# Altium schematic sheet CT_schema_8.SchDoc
size 252 x 159 mm
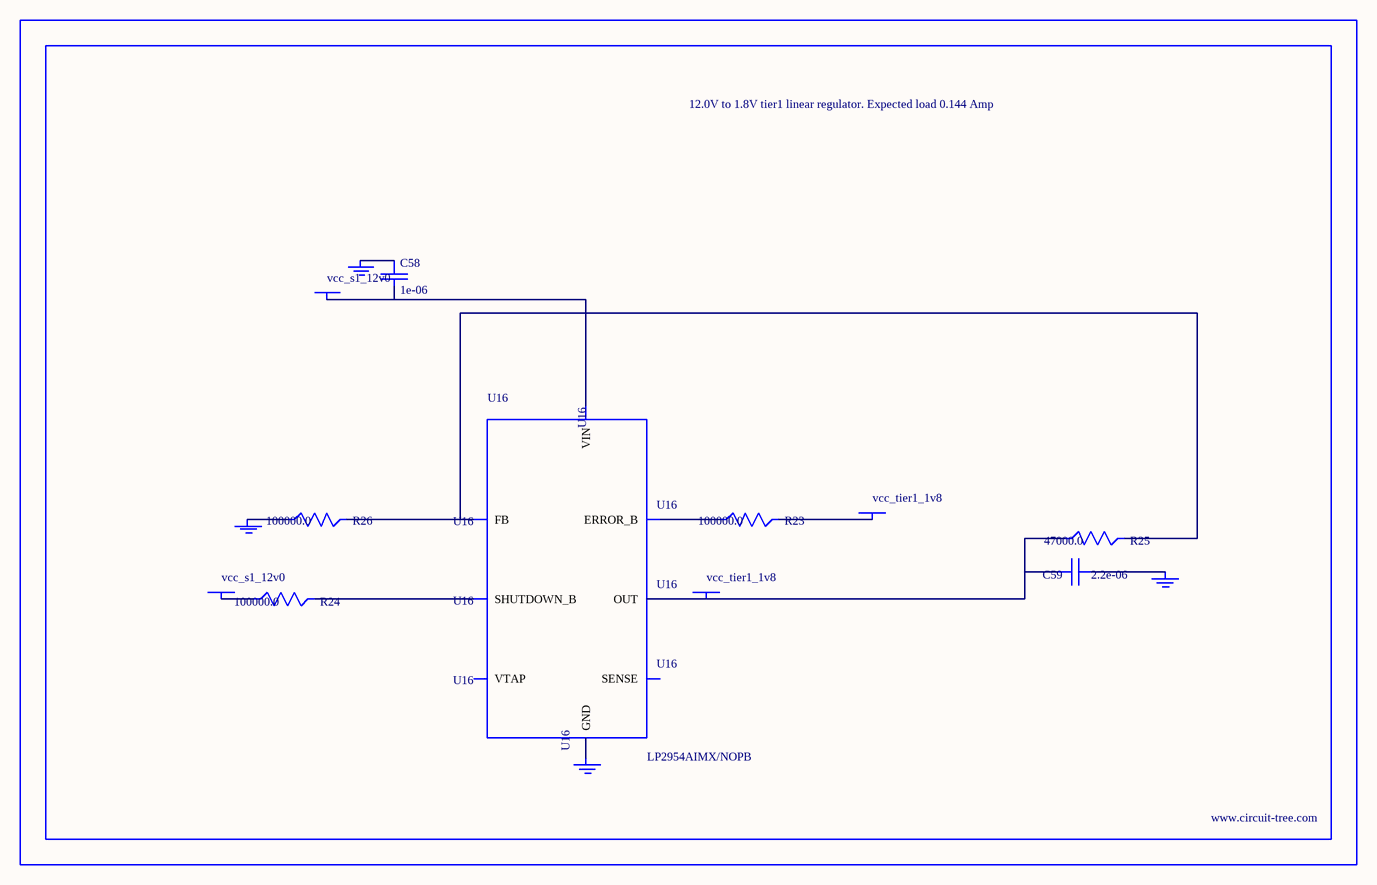
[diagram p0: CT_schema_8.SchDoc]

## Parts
BORDER7  (no value)
C58  1e-06  [EXV-9B]
C59  2.2e-06  [EXV-9B]
GND_INSTANCE_7_0  (no value)
GND_INSTANCE_7_1  (no value)
GND_INSTANCE_7_2  (no value)
GND_INSTANCE_7_3  (no value)
POWER_INSTANCE_7_0  vcc_s1_12v0
POWER_INSTANCE_7_1  vcc_tier1_1v8
POWER_INSTANCE_7_2  vcc_s1_12v0
POWER_INSTANCE_7_3  vcc_tier1_1v8
R23  100000.0  [R0603]
R24  100000.0  [R0603]
R25  47000.0  [R0603]
R26  100000.0  [R0603]
U16  LP2954AIMX/NOPB  [LP2954]

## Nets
NetC58_1: C58.1 GND_INSTANCE_7_2.0(GND)
NetC58_2: C58.2 POWER_INSTANCE_7_2.0(PWR) U16.8(VIN)
NetC59_1: C59.1 GND_INSTANCE_7_0.0(GND)
NetC59_2: C59.2 POWER_INSTANCE_7_3.0(PWR) R25.1 U16.1(OUT)
NetGND_INSTANCE_7_1_0: GND_INSTANCE_7_1.0(GND) R26.1
NetGND_INSTANCE_7_3_0: GND_INSTANCE_7_3.0(GND) U16.4(GND)
NetPOWER_INSTANCE_7_0_0: POWER_INSTANCE_7_0.0(PWR) R24.1
NetPOWER_INSTANCE_7_1_0: POWER_INSTANCE_7_1.0(PWR) R23.2
NetR23_1: R23.1 U16.5(ERROR_B)
NetR24_2: R24.2 U16.3(SHUTDOWN_B)
NetR25_2: R25.2 R26.2 U16.7(FB)

Not connected (* = marked no-connect by the designer): U16 2(SENSE) 6(VTAP)

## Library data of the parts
BORDER7 = BORDER_PAGE7
C58 = EDK105M050A9BAA
C59 = EDK225M050A9BAA
GND_INSTANCE_7_0-GND_INSTANCE_7_3 = GND
POWER_INSTANCE_7_0-POWER_INSTANCE_7_3 = PWR
R23 R24 R26 = RC0603JR-07100KL
R25 = RC0603JR-0747KL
